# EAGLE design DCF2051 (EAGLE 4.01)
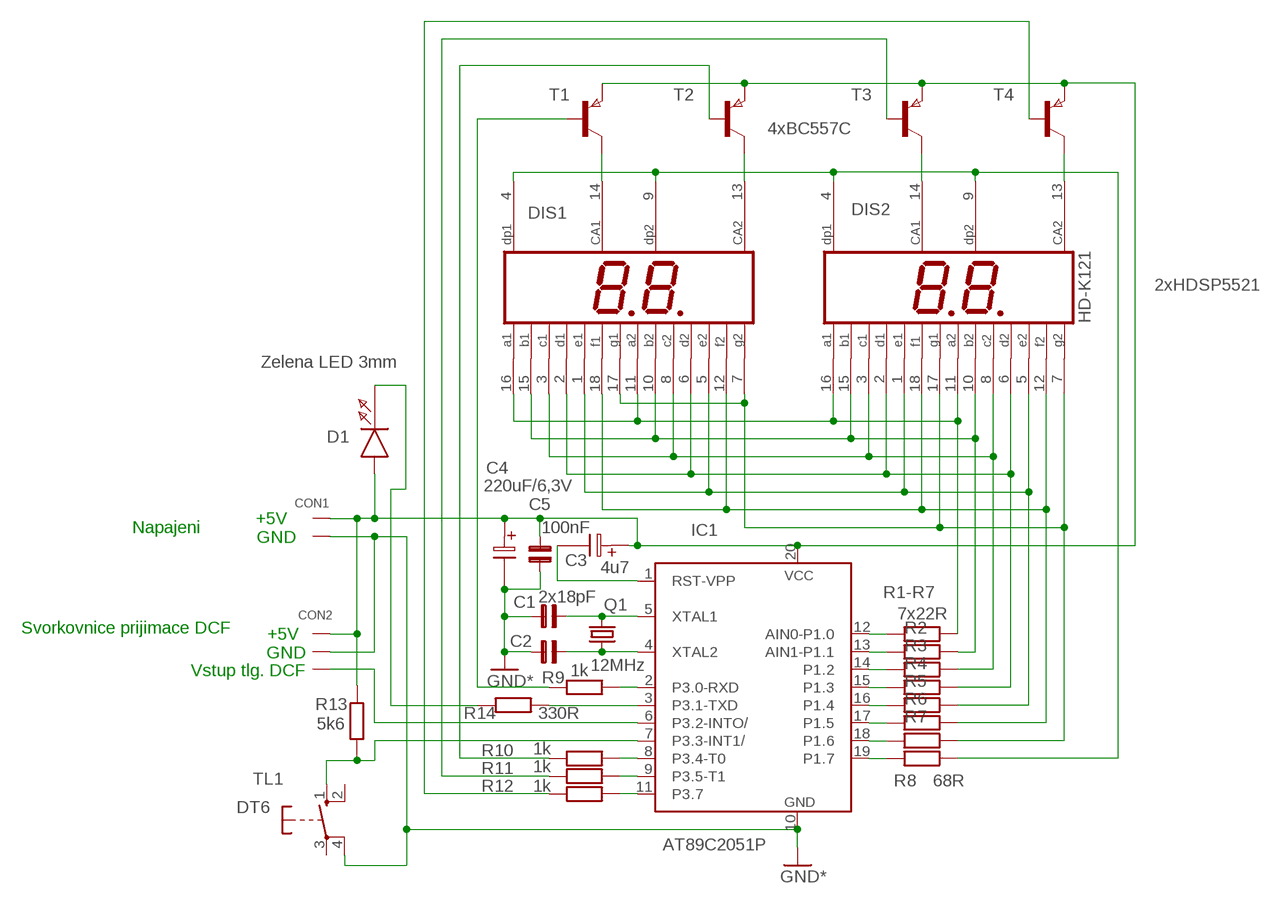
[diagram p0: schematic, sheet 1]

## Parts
C1  2x18pF  C5/3  [C5B3]
C2  C5/3  [C5B3]
C3  4u7  CT04  [CT04]
C4  220uF/6,3V  E5X11  [E50]
C5  100nF  C5/3  [C5B3]
CON1  ARK550/2  [ARK550/2]
CON2  ARK550/3  [ARK550/3]
D1  Zelena LED 3mm  LED3MMZELE  [LED3]
DIS1  2xHDSP5521  HD-K121  [HDSP-R]
DIS2  HD-K121  [HDSP-R]
IC1  AT89C2051P  [DIL20]
Q1  12MHz  HC49U-V  [HC49U-V]
R1-R7  7x22R  RR  [RR]
R2  RR  [RR]
R3  RR  [RR]
R4  RR  [RR]
R5  RR  [RR]
R6  RR  [RR]
R7  RR  [RR]
R8  68R  RR  [RR]
R9  1k  RR  [RR]
R10  1k  RR  [RR]
R11  1k  RR  [RR]
R12  1k  RR  [RR]
R13  5k6  RR  [RR]
R14  330R  RR  [RR]
T1  4xBC557C  BC557C  [TO-92C]
T2  BC557C  [TO-92C]
T3  BC557C  [TO-92C]
T4  BC557C  [TO-92C]
TL1  DT6  [DT6]

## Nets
GND: C1.1 C2.1 C4.2 C5.1 CON1.2 CON2.2 IC1.10(GND) TL1.4 ; supply symbol labelled GND*
N$1: C1.2 IC1.5(XTAL1) Q1.2
N$2: C2.2 IC1.4(XTAL2) Q1.1
N$3: IC1.12(AIN0-P1.0) R1-R7.1
N$4: IC1.13(AIN1-P1.1) R2.1
N$5: DIS1.11(A2) DIS1.16(A1) DIS2.11(A2) DIS2.16(A1) R1-R7.2
N$6: IC1.14(P1.2) R3.1
N$7: IC1.15(P1.3) R4.1
N$8: DIS1.10(B2) DIS1.15(B1) DIS2.10(B2) DIS2.15(B1) R2.2
N$9: IC1.16(P1.4) R5.1
N$10: DIS1.3(C1) DIS1.8(C2) DIS2.3(C1) DIS2.8(C2) R3.2
N$11: IC1.17(P1.5) R6.1
N$12: DIS1.2(D1) DIS1.6(D2) DIS2.2(D1) DIS2.6(D2) R4.2
N$13: IC1.18(P1.6) R7.1
N$14: DIS1.1(E1) DIS1.5(E2) DIS2.1(E1) DIS2.5(E2) R5.2
N$15: IC1.19(P1.7) R8.1
N$16: DIS1.12(F2) DIS1.18(F1) DIS2.12(F2) DIS2.18(F1) R6.2
N$17: IC1.2(P3.0-RXD) R9.2
N$18: DIS1.7(G2) DIS1.17(G1) DIS2.7(G2) DIS2.17(G1) R7.2
N$19: IC1.8(P3.4-T0) R10.2
N$20: DIS1.4(DP1) DIS1.9(DP2) DIS2.4(DP1) DIS2.9(DP2) R8.2
N$21: IC1.9(P3.5-T1) R11.2
N$22: IC1.11(P3.7) R12.2
N$23: DIS1.14(CA1) T1.3(C)
N$24: DIS1.13(CA2) T2.3(C)
N$25: DIS2.14(CA1) T3.3(C)
N$26: DIS2.13(CA2) T4.3(C)
N$27: C3.1 C4.1 C5.2 CON1.1 CON2.1 D1.A IC1.20(VCC) R13.1 T1.1(E) T2.1(E) T3.1(E) T4.1(E)
N$28: R11.1 T3.2(B)
N$29: R9.1 T1.2(B)
N$30: R10.1 T2.2(B)
N$31: R12.1 T4.2(B)
N$32: IC1.7(P3.3-INT1/) R13.2 TL1.1
N$33: C3.2 IC1.1(RST-VPP)
N$35: IC1.3(P3.1-TXD) R14.2
N$36: CON2.3 IC1.6(P3.2-INTO/)
N$37: D1.K R14.1
Unconnected: TL1.2 TL1.3

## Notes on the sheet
- +5V
- Napajeni
- GND
- Svorkovnice prijimace DCF
- +5V
- GND
- Vstup tlg. DCF

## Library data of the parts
C1 C2 C5 = capacitor-wima:C: CAPACITOR
C3 = GM99:CT04
C4 = GM99:E5X11
CON1 = GM99:ARK550/2
CON2 = GM99:ARK550/3
D1 = GM99:LED3MMZELE
DIS1 DIS2 = display-hp:HD-K121: LED DISPLAY 2 x 1 character 7 segment, decimal points right
IC1 = atmel:AT89C2051: 80C31 MICROCONTROLLER 2 Kbytes FLASH 2.7 V
Q1 = crystal:HC49U-V: CRYSTAL
R1-R7 R2-R14 = GM99:RR
T1-T4 = GM99:BC557C
TL1 = switch-misc:DT6: ITT SWITCH

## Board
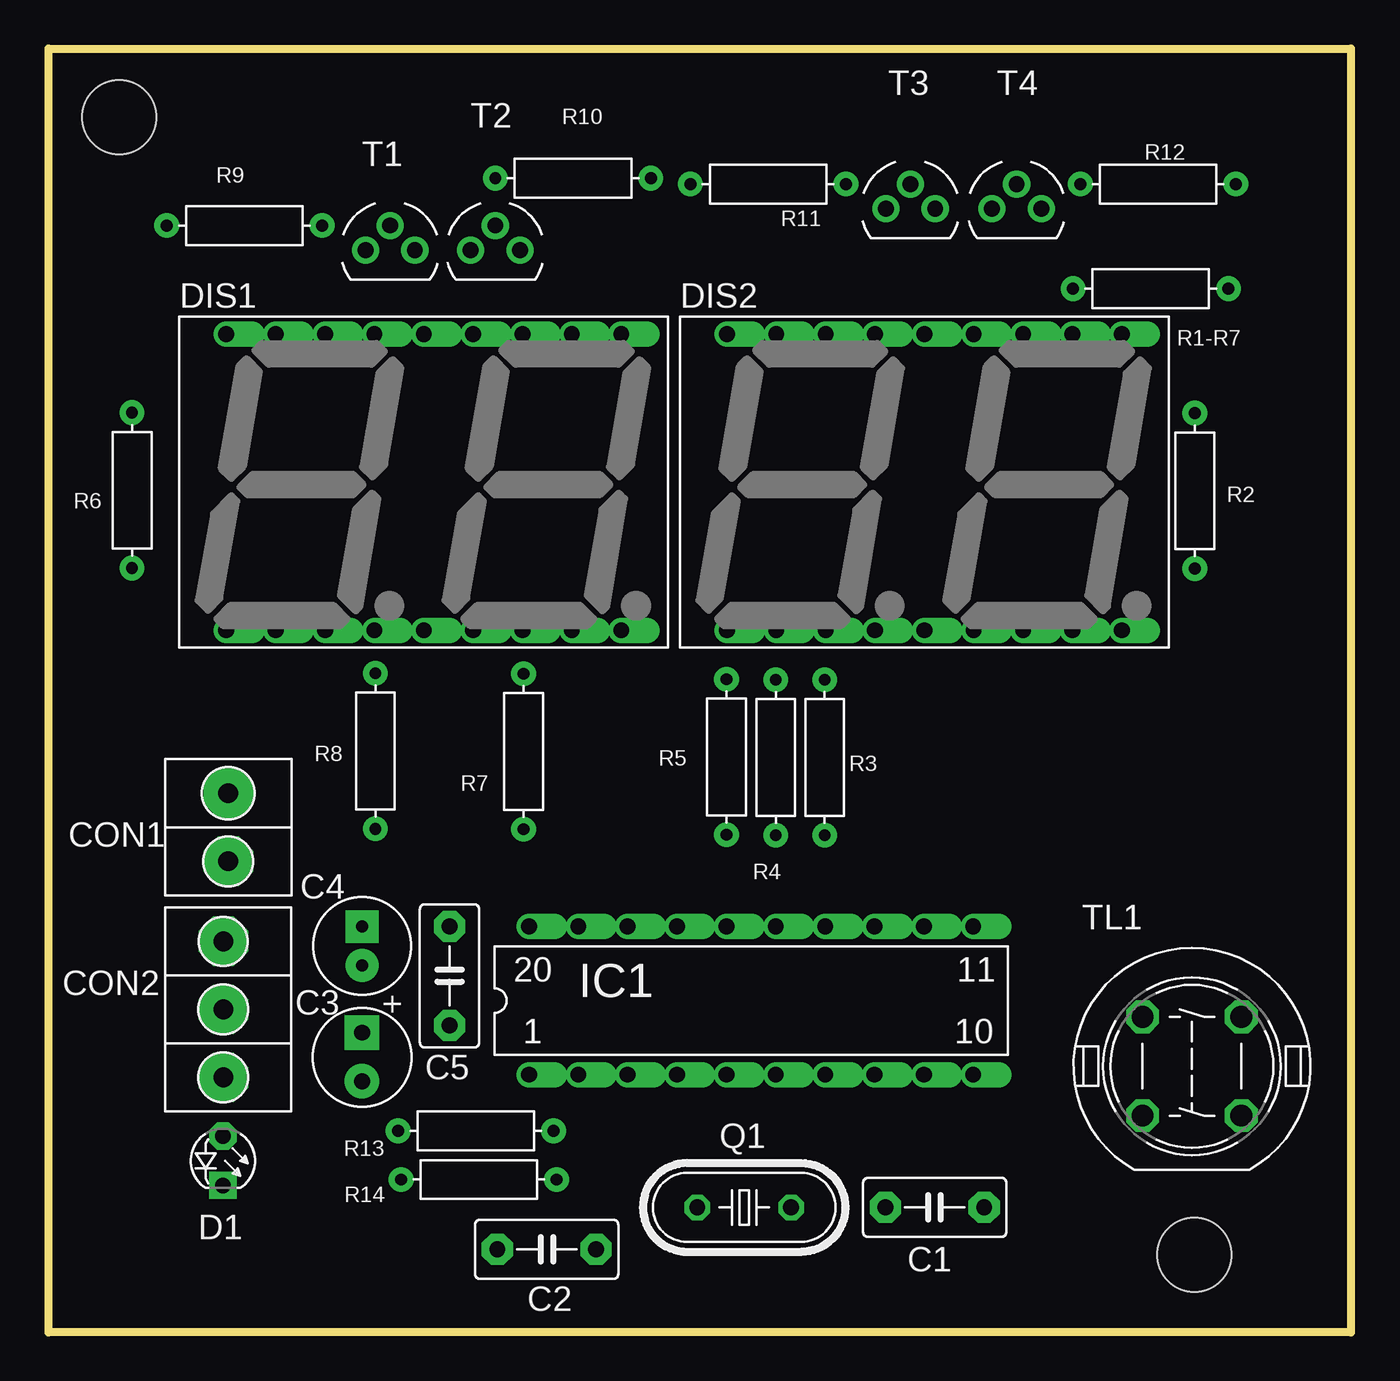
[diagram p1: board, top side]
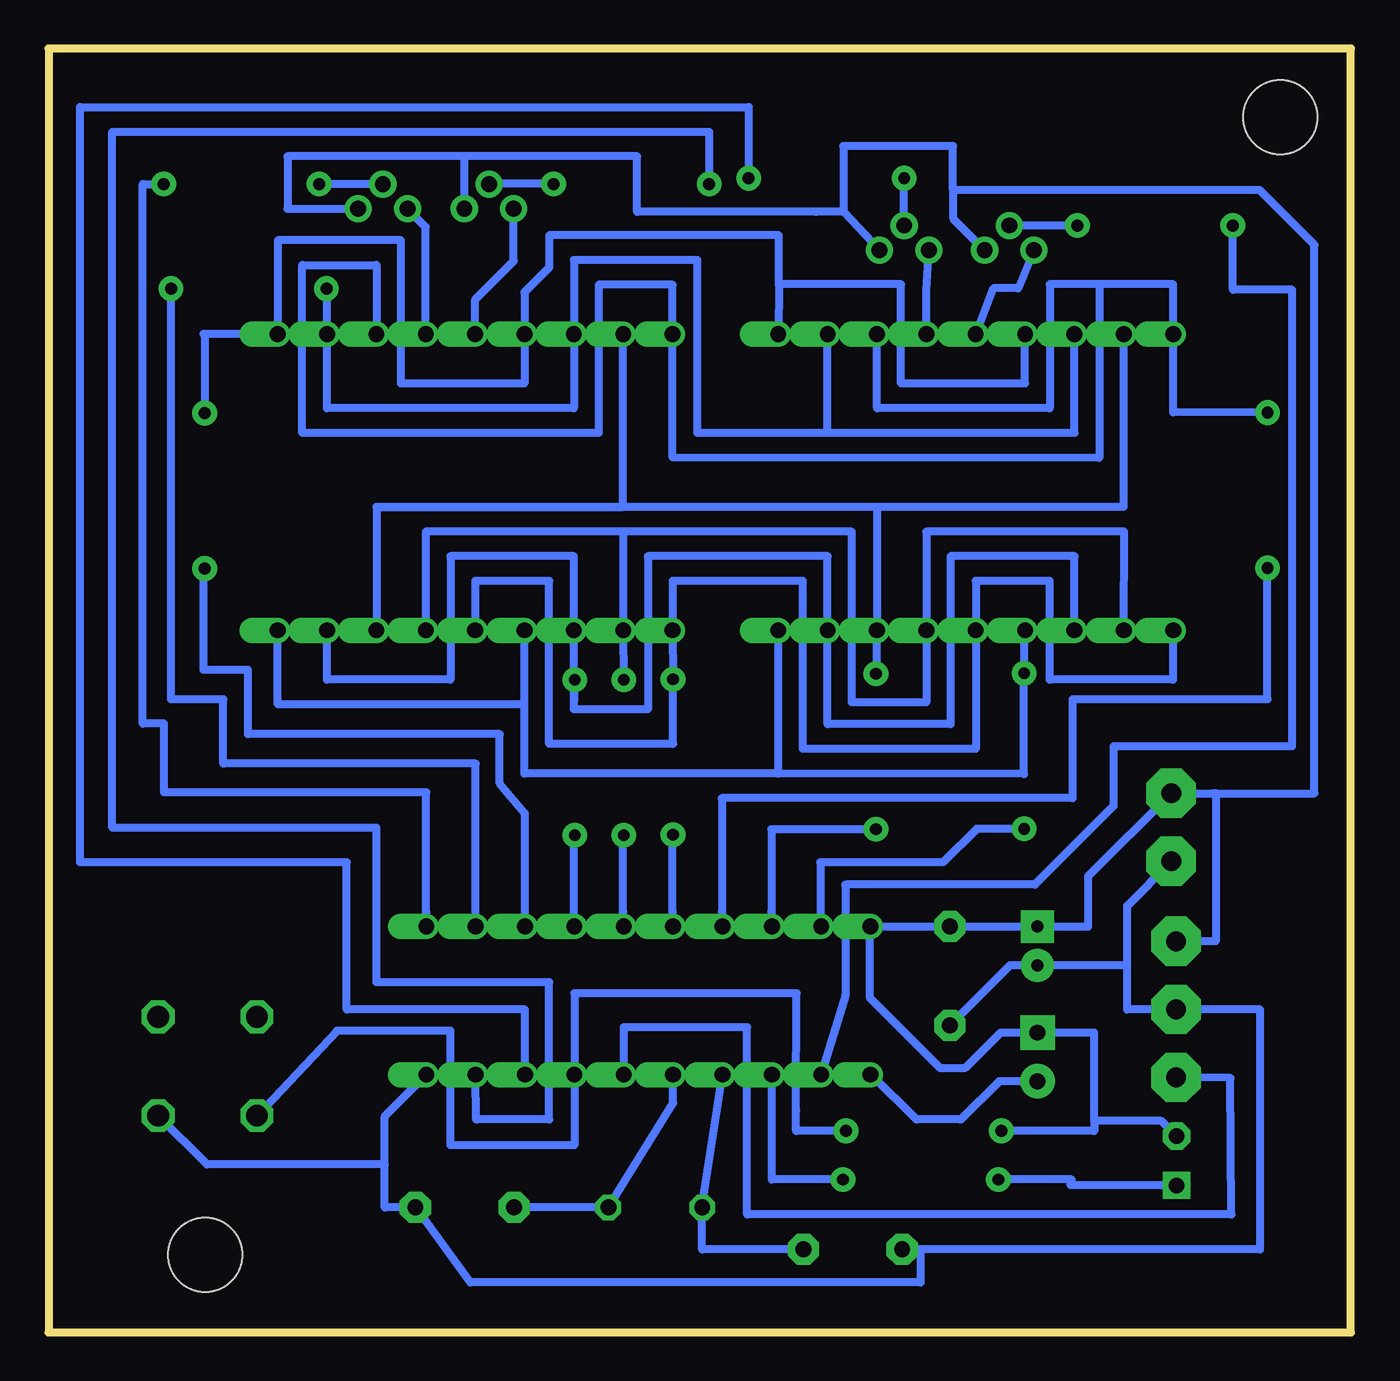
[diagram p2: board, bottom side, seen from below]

Size 67.01 x 66.05 mm. Coordinates in mm from the lower left corner, seen from the top.
Outline: 0,0 0,66.05 67,66.05 67,0 0,0
Copper layers used: Bottom
Holes 3.81 mm at 58.94,3.99 3.63,62.52

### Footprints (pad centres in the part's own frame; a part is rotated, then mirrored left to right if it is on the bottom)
C5B3 = drill 0.813 pad 1.6 octagon: 1 -2.54,0; 2 2.54,0
CT04 = drill 0.813 pad 1.778 square: 1 0,0 | drill 0.813 pad 1.778 round: 2 2.5,0
E50 = drill 0.61 pad 1.676 square: 1 0,0 | drill 0.61 pad 1.676 round: 2 2,0
ARK550/2 = drill 1.016 pad 2.54 octagon: 1 0,0; 2 3.5,0
ARK550/3 = drill 1.016 pad 2.54 octagon: 1 0,0; 2 3.5,0; 3 7,0
LED3 = drill 0.813 pad 1.397 octagon: A -1.27,0 | drill 0.813 pad 1.397 square: K 1.27,0
HDSP-R = drill 0.813 offset: 1 -10.16,-7.62; 2 -7.62,-7.62; 3 -5.08,-7.62; 4 -2.54,-7.62; 5 0,-7.62; 6 2.54,-7.62; 7 5.08,-7.62; 8 7.62,-7.62; 9 10.16,-7.62; 10 10.16,7.62; 11 7.62,7.62; 12 5.08,7.62; 13 2.54,7.62; 14 0,7.62; 15 -2.54,7.62; 16 -5.08,7.62; 17 -7.62,7.62; 18 -10.16,7.62
DIL20 = drill 0.813 offset: 1 -11.43,-3.81; 2 -8.89,-3.81; 3 -6.35,-3.81; 4 -3.81,-3.81; 5 -1.27,-3.81; 6 1.27,-3.81; 7 3.81,-3.81; 8 6.35,-3.81; 9 8.89,-3.81; 10 11.43,-3.81; 11 11.43,3.81; 12 8.89,3.81; 13 6.35,3.81; 14 3.81,3.81; 15 1.27,3.81; 16 -1.27,3.81; 17 -3.81,3.81; 18 -6.35,3.81; 19 -8.89,3.81; 20 -11.43,3.81
HC49U-V = drill 0.813 octagon: 1 -2.413,0; 2 2.413,0
RR = drill 0.61 pad 1.27 round: 1 0,0; 2 8,0
TO-92C = drill 0.813 pad 1.397 round: 1 0,0; 2 1.27,1.27; 3 0,2.54
DT6 = drill 1.118 octagon: 1 -2.54,2.54; 2 2.54,2.54; 3 2.54,-2.54; 4 -2.54,-2.54

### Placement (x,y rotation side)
C1  45.59,6.43 180 top
C2  25.63,4.27 0 top
C3  16.13,15.42 270 top
C4  16.13,20.88 270 top
C5  20.62,18.34 90 top
CON1  9.25,27.74 270 top
CON2  8.99,20.12 270 top
D1  8.97,8.82 270 top
DIS1  19.3,43.74 0 top
DIS2  45.06,43.74 0 top
IC1  36.14,17.07 0 top
Q1  35.79,6.43 0 top
R1-R7  60.71,53.7 180 top
R2  58.98,39.29 90 top
R3  39.93,25.58 90 top
R4  37.41,25.58 90 top
R5  34.87,25.6 90 top
R6  4.29,39.32 90 top
R7  24.43,25.88 90 top
R8  16.81,25.91 90 top
R9  14.07,56.95 180 top
R10  22.99,59.39 0 top
R11  41.02,59.08 180 top
R12  53.09,59.08 0 top
R13  17.98,10.36 0 top
R14  18.14,7.86 0 top
T1  18.85,55.68 90 top
T2  24.26,55.68 90 top
T3  45.62,57.81 90 top
T4  51.08,57.81 90 top
TL1  58.83,13.69 90 top

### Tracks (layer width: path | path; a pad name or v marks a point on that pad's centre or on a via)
GND
  Bottom 0.406: 11.51,16.69 11.51,16.64 | CON1.2 11.51,21.95 11.51,16.69 | 20.65,15.77 C5.1 17.55,18.88 C4.2 12.16,18.88 | 12.16,18.88 12.14,18.9 | 12.16,18.88 11.51,18.88 11.51,16.69 | 11.51,16.62 11.51,16.69 | 11.51,16.62 CON2.2 6.68,16.62 4.67,16.61 4.67,4.27 22.15,4.27 | 11.51,16.62 11.51,16.61 | IC1.10 49.71,11.12 49.71,11.07 49.71,8.64 | 49.71,8.64 49.71,6.43 C1.1 45.31,2.56 22.15,2.56 22.15,4.27 | 22.15,4.27 22.17,4.27 | 22.17,4.27 C2.1 | 22.17,4.27 22.17,4.24 | TL1.4 58.85,8.64 49.71,8.64
N$1
  Bottom 0.406: IC1.5 34.87,11.79 Q1.2 C1.2
N$2
  Bottom 0.406: IC1.4 33.38,6.45 Q1.1 33.38,4.27 C2.2 28.14,4.27
N$3
  Bottom 0.406: IC1.12 45.03,29.26 58.01,29.26 58.01,32.56 60.71,32.56 R1-R7.1
N$4
  Bottom 0.406: IC1.13 42.49,26.72 42.52,26.72 43.79,28.25 43.79,30.79 56.74,30.79 56.74,34.09 59.03,34.09 59.03,39.29 | 59.03,39.29 59.03,39.42 | 59.03,39.29 R2.1
N$5
  Bottom 0.406: DIS1.16 14.22,46.28 26.92,46.28 | 26.92,46.28 DIS1.11 | 26.92,46.28 33.63,46.28 33.63,55.17 39.98,55.17 DIS2.16 39.98,47.55 52.68,47.55 DIS2.11 52.68,53.39 52.71,53.39 | 52.71,53.39 52.93,53.39 | 52.71,53.39 R1-R7.2
N$6
  Bottom 0.406: 39.98,25.58 39.98,25.7 | 39.98,25.58 R3.1 | IC1.14 39.98,21.64 39.98,25.58
N$7
  Bottom 0.406: 37.44,25.58 37.44,25.7 | 37.44,25.58 R4.1 | IC1.15 37.44,21.64 37.44,25.58
N$8
  Bottom 0.406: 29.44,53.92 DIS1.10 | DIS1.15 16.76,48.82 23.14,48.82 23.14,53.92 29.44,53.92 | R2.2 58.98,51.31 59.03,51.36 DIS2.10 55.22,56.19 48.87,56.19 48.87,48.82 42.52,48.82 DIS2.15 42.52,53.52 41.25,54.79 41.25,56.44 29.44,56.44 29.44,53.92
N$9
  Bottom 0.406: 34.9,25.6 34.9,25.7 | 34.9,25.6 R5.1 | IC1.16 34.9,21.64 34.9,25.6
N$10
  Bottom 0.406: DIS1.3 14.22,39.93 20.6,39.93 20.6,31.29 26.92,31.29 DIS1.8 26.92,39.93 36.17,39.93 36.17,32.05 39.98,32.05 | 39.98,32.05 DIS2.3 39.98,39.93 46.33,39.93 46.33,33.58 52.68,33.58 DIS2.8 | 39.98,32.05 R3.2
N$11
  Bottom 0.406: R6.1 4.29,32.56 14.33,32.56 14.33,27.48 32.36,27.48 32.36,21.64 IC1.17
N$12
  Bottom 0.406: DIS1.2 11.66,41.2 21.84,41.2 DIS1.6 21.84,32.41 25.68,32.41 25.68,41.2 37.44,41.2 | 37.44,41.2 47.6,41.2 DIS2.6 | 37.44,41.2 DIS2.2 R4.2
N$13
  Bottom 0.406: IC1.18 29.82,21.64 29.82,25.88 R7.1
N$14
  Bottom 0.406: DIS1.1 9.14,33.58 15.49,33.58 15.49,38.66 19.3,38.66 DIS1.5 19.3,30.02 28.19,30.02 28.19,38.66 34.9,38.66 DIS2.1 R5.2 34.9,33.6 34.9,30.28 | 34.9,30.28 41.25,30.28 41.25,38.66 45.06,38.66 DIS2.5 | 34.9,30.28 34.87,30.28
N$15
  Bottom 0.406: IC1.19 27.28,21.64 27.28,24.18 | R8.1 19.25,25.91 20.98,24.18 27.28,24.18 | 27.28,24.18 27.3,24.18
N$16
  Bottom 0.406: 12.95,53.92 12.95,44.98 34.9,45.01 DIS2.18 34.9,53.9 38.71,53.9 38.71,46.28 53.95,46.28 53.95,54.91 50.14,54.91 DIS2.12 | DIS1.12 24.38,47.55 15.49,47.55 15.49,53.92 12.95,53.92 | R6.2 9.14,47.34 DIS1.18 9.14,53.92 12.95,53.92
N$17
  Bottom 0.406: R9.2 6.07,53.65 3.02,53.65 3.02,30.15 12.22,30.15 12.22,27.08 16.26,23.04 25.98,23.04 26.01,23.01 | 26.01,23.01 26.01,17.35 IC1.2 | 26.01,23.01 26.01,23.04
N$18
  Bottom 0.406: DIS1.17 11.68,42.47 24.38,42.47 | 24.38,42.47 DIS1.7 R7.2 | 24.38,42.47 50.14,42.47 | 50.14,42.47 DIS2.7 | DIS2.17 37.44,42.47 50.14,42.47
N$19
  Bottom 0.406: IC1.8 42.49,16.61 51.66,16.61 51.66,24.18 65.38,24.18 65.38,63.04 30.99,63.04 R10.2
N$20
  Bottom 0.406: DIS1.4 R8.2 16.82,28.73 29.46,28.75 | 29.46,28.75 DIS1.9 | 29.46,28.75 42.52,28.75 42.52,32.31 | 42.52,32.31 DIS2.4 | DIS2.9 55.22,32.31 42.52,32.31
N$21
  Bottom 0.406: R11.2 33.02,61.77 63.73,61.77 63.73,25.96 50.14,25.96 50.14,18.01 41.25,18.01 41.25,10.95 45.01,10.95 IC1.9
N$22
  Bottom 0.406: R12.2 62.15,59.08 62.15,31.32 61.06,31.32 61.06,29.36 61.06,27.79 47.57,27.79 IC1.11 47.57,21.61
N$23
  Bottom 0.406: T1.3 17.12,53.72 18.39,53.72 DIS1.14
N$24
  Bottom 0.406: DIS1.13 21.84,53.57 T2.3
N$25
  Bottom 0.406: T3.3 43.08,55.12 45.06,53.14 DIS2.14
N$26
  Bottom 0.406: T4.3 47.6,56.87 DIS2.13
N$27
  Bottom 0.406: T4.1 54.71,57.81 54.71,60.5 45.62,60.5 | 45.62,60.5 T3.1 | 45.62,60.5 36.73,60.5 36.73,57.66 27.53,57.66 | 7.09,27.74 CON1.1 13.51,23.47 13.51,20.88 C4.1 C5.2 IC1.20 24.74,20.88 24.74,17.2 21.13,13.59 19.86,13.59 18.03,15.42 C3.1 13.21,15.42 13.21,14.73 | CON2.1 6.96,20.12 6.96,27.74 7.09,27.74 | T1.1 20.47,57.3 20.47,58.78 | 20.47,58.78 20.47,61.04 26.11,61.04 26.11,57.66 | 26.11,57.66 T2.1 | 7.09,27.74 1.88,27.74 1.88,55.96 4.7,58.78 20.47,58.78 | R13.1 13.21,10.36 13.21,10.87 | 13.21,10.87 13.21,14.73 | 13.21,14.73 13.21,14.76 | 27.53,57.66 27.51,57.66 | 26.11,57.66 27.53,57.66 | D1.A 9.75,10.87 13.21,10.87
N$28
  Bottom 0.406: R11.1 41.02,59.11 44.32,59.11 T3.2
N$29
  Bottom 0.406: R9.1 T1.2
N$30
  Bottom 0.406: 22.99,56.92 T2.2 R10.1
N$31
  Bottom 0.406: 49.78,59.08 T4.2 R12.1
N$32
  Bottom 0.406: R13.2 28.55,10.36 28.55,11.43 28.52,17.45 39.95,17.45 IC1.7 39.95,9.63 46.33,9.63 46.33,15.52 52.17,15.52 TL1.1
N$33
  Bottom 0.406: C3.2 18.1,12.92 20.07,10.95 22.35,10.95 24.66,13.26 IC1.1
N$35
  Bottom 0.406: IC1.3 29.79,8.1 29.8,7.87 29.79,7.87 29.79,7.86 R14.2
N$36
  Bottom 0.406: CON2.3 6.2,13.08 6.15,6.07 31.06,6.07 31.06,15.7 37.41,15.7 IC1.6
N$37
  Bottom 0.406: R14.1 14.38,7.86 14.43,7.57 8.99,7.57 8.99,7.55 | 8.99,7.55 8.99,7.54 | D1.K 8.99,7.55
